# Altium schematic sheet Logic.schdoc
size 274 x 153 mm
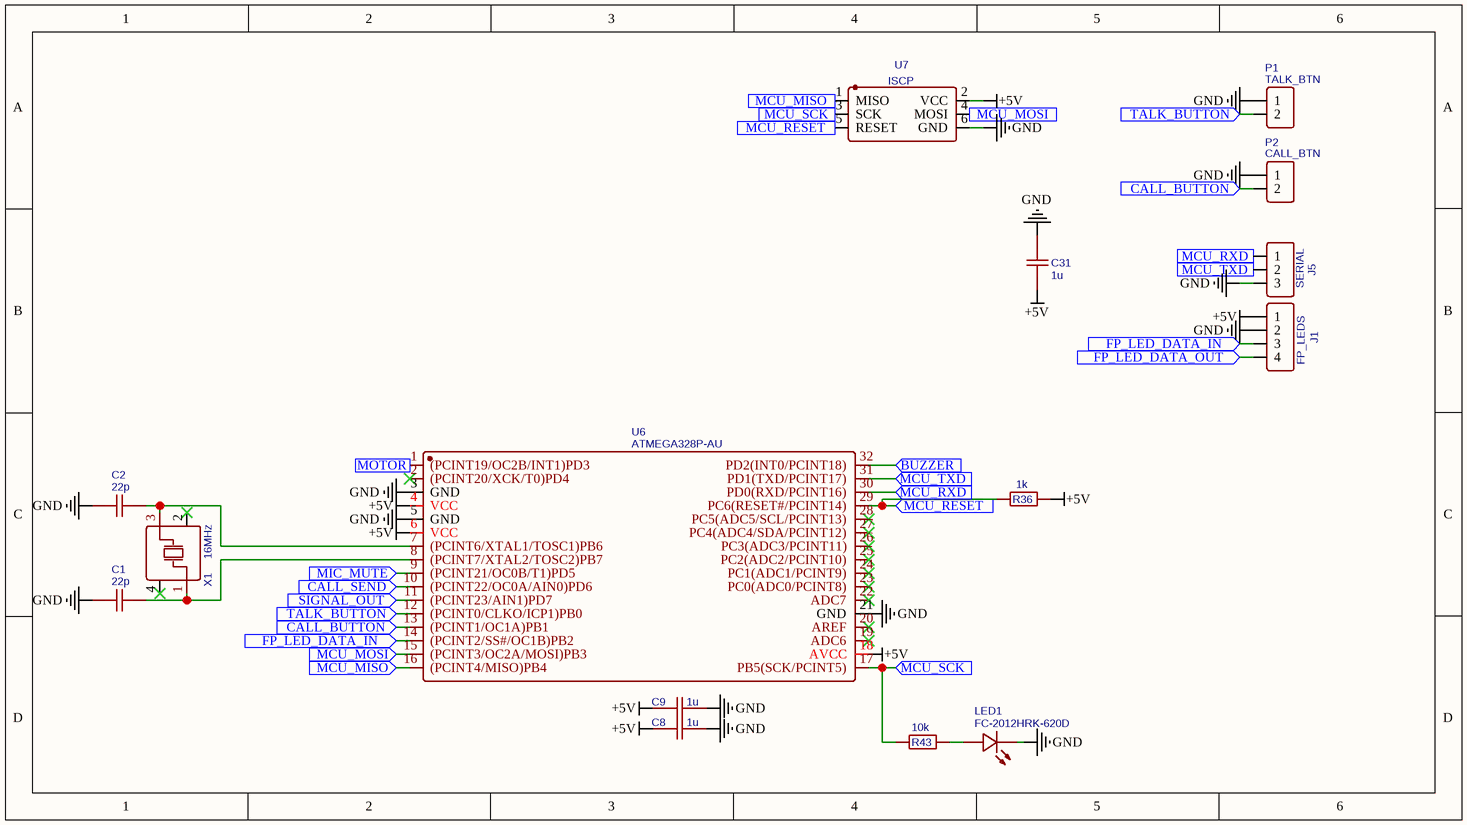
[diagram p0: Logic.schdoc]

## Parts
C1  22p  [C0603]
C2  22p  [C0603]
C8  1u  [C0603]
C9  1u  [C0603]
C31  1u  [C0603]
J1  FP_LEDS  [HDR-M-2.54_1X4]
J5  SERIAL  [HDR-M-2.54_1X3]
LED1  FC-2012HRK-620D  [LED0805-RD_RED]
P1  TALK_BTN  [CONN-TH_2P-P5.00]
P2  CALL_BTN  [CONN-TH_2P-P5.00]
R36  1k  [R1206]
R43  10k  [R1206]
U6  ATMEGA328P-AU  [TQFP-32_L7.0-W7.0-P0.80-LS9.0-BL]
U7  ISCP  [SPI HEADER]
X1  16MHz  [OSC-SMD_4P-L3.2-W2.5-BL]

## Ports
BUZZER (in), CALL_BUTTON (in), CALL_SEND (in), FP_LED_DATA_IN (in), FP_LED_DATA_OUT (in), MCU_MISO (in), MCU_MOSI (in), MCU_RESET (in), MCU_RXD (in), MCU_SCK (in), MCU_TXD (in), MIC_MUTE (in), MOTOR (in), SIGNAL_OUT (in), TALK_BUTTON (in)

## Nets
+5V: C8.1 C9.1 C31.1 J1.1 R36.2 U6.4(VCC) U6.6(VCC) U6.18(AVCC) U7.2(VCC)
GND: C1.1 C2.1 C8.2 C9.2 C31.2 J1.2 J5.3 LED1.1(-) P1.1 P2.1 U6.3(GND) U6.5(GND) U6.21(GND) U7.6(GND)
BUZZER: U6.32(PD2(INT0/PCINT18)) ; port BUZZER
CALL_BUTTON: P2.2 U6.13((PCINT1/OC1A)PB1) ; port CALL_BUTTON
CALL_SEND: U6.10((PCINT22/OC0A/AIN0)PD6) ; port CALL_SEND
FP_LED_DATA_IN: J1.3 U6.14((PCINT2/SS#/OC1B)PB2) ; port FP_LED_DATA_IN
FP_LED_DATA_OUT: J1.4 ; port FP_LED_DATA_OUT
MCU_MISO: U6.16((PCINT4/MISO)PB4) U7.1(MISO) ; port MCU_MISO
MCU_MOSI: U6.15((PCINT3/OC2A/MOSI)PB3) U7.4(MOSI) ; port MCU_MOSI
MCU_RESET: R36.1 U6.29(PC6(RESET#/PCINT14)) U7.5(RESET) ; port MCU_RESET
MCU_RXD: J5.1 U6.30(PD0(RXD/PCINT16)) ; port MCU_RXD
MCU_SCK: R43.2 U6.17(PB5(SCK/PCINT5)) U7.3(SCK) ; port MCU_SCK
MCU_TXD: J5.2 U6.31(PD1(TXD/PCINT17)) ; port MCU_TXD
MIC_MUTE: U6.9((PCINT21/OC0B/T1)PD5) ; port MIC_MUTE
MOTOR: U6.1((PCINT19/OC2B/INT1)PD3) ; port MOTOR
SIGNAL_OUT: U6.11((PCINT23/AIN1)PD7) ; port SIGNAL_OUT
TALK_BUTTON: P1.2 U6.12((PCINT0/CLKO/ICP1)PB0) ; port TALK_BUTTON
NetC1_2: C1.2 U6.8((PCINT7/XTAL2/TOSC2)PB7) X1.1(OSC1)
NetC2_2: C2.2 U6.7((PCINT6/XTAL1/TOSC1)PB6) X1.3(OSC2)
NetLED1_2: LED1.2(+) R43.1

Not connected (* = marked no-connect by the designer): U6 2((PCINT20/XCK/T0)PD4)* 19(ADC6)* 20(AREF)* 22(ADC7)* 23(PC0(ADC0/PCINT8))* 24(PC1(ADC1/PCINT9))* 25(PC2(ADC2/PCINT10))* 26(PC3(ADC3/PCINT11))* 27(PC4(ADC4/SDA/PCINT12))* 28(PC5(ADC5/SCL/PCINT13))*; X1 2(GND)* 4(GND)*

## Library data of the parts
C1 C2 = 22p: BOM_Manufacturer Part: CL10C220JB8NNNC; BOM_Manufacturer: SAMSUNG(三星); nameAlias: Value(F); Contributor: LCEDA_Lib
C8 C9 C31 = 1u: BOM_Manufacturer Part: CL10A105KB8NNNC; BOM_Manufacturer: SAMSUNG(三星); nameAlias: Value(F); Contributor: LCEDA_Lib
J1 = FP_LEDS: Contributor: LCEDA_Lib
J5 = SERIAL: Contributor: LCEDA_Lib
LED1 = FC-2012HRK-620D: BOM_Manufacturer: 国星光电; BOM_Manufacturer Part: NCD0805R1
P1 = TALK_BTN: Contributor: LCEDA_Lib
P2 = CALL_BTN: Contributor: LCEDA_Lib
R36 = 1k: BOM_Manufacturer Part: 1206W4F1001T5E; BOM_Manufacturer: UNI-ROYAL(厚声); nameAlias: Value(Ω); Contributor: LCEDA_Lib
R43 = 10k: BOM_Manufacturer Part: 1206W4F1002T5E; BOM_Manufacturer: UNI-ROYAL(厚声); nameAlias: Value(Ω); Contributor: LCEDA_Lib
U6 = ATMEGA328P-AU: BOM_Manufacturer: MICROCHIP(美国微芯)
U7 = ISCP: Contributor: xend
X1 = 16MHz: BOM_Manufacturer: YXC(扬兴晶振); BOM_Manufacturer Part: X322516MLB4SI; nameAlias: Frequency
